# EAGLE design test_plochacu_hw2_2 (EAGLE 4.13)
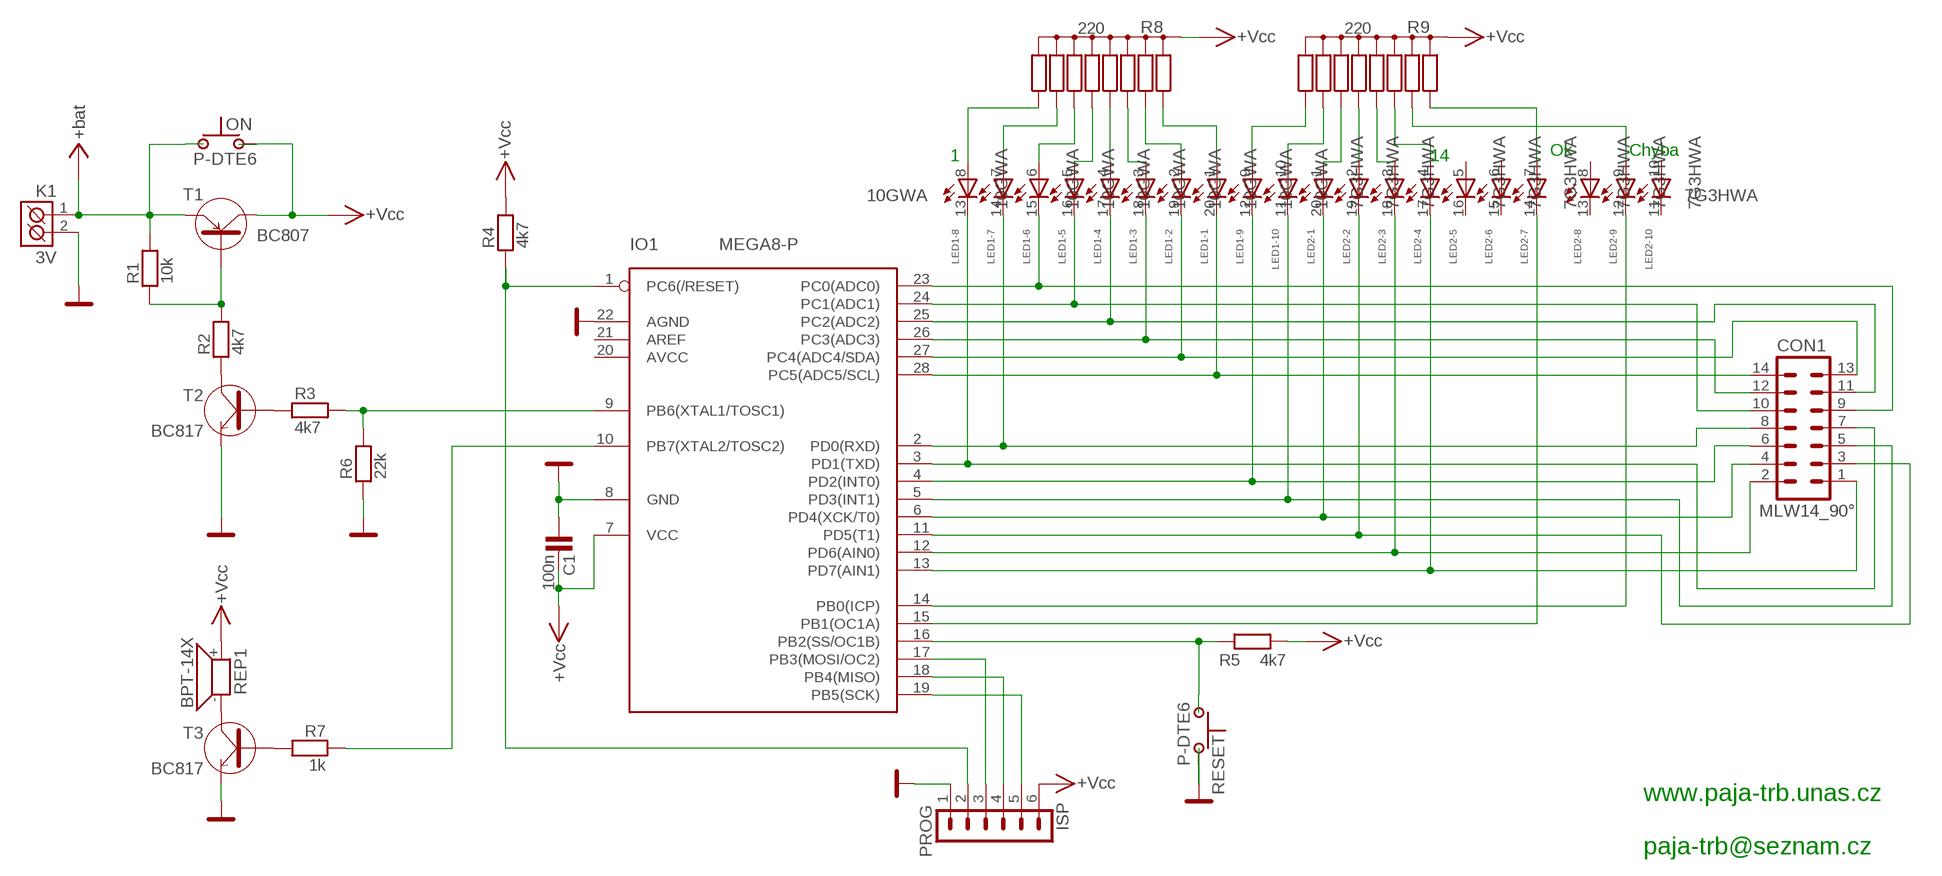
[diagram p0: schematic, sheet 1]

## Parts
C1  100n  C-KERAMIK_SMD_1206  [1206]
CON1  MLW14_90°  [MLW14A]
IO1  MEGA8-P  [DIL28-3]
K1  3V  ARK500/2  [ARK500/2]
LED1  10GWA  LB10  [LB10]
LED2  7G3HWA  LB10  [LB10]
ON  P-DTE6  P-DT6_HRANATY_HRANATY  [P-DTE6]
PROG  ISP  S1G6_JUMP  [S1G6_JUM]
R1  10k  R_SMD_1206  [1206]
R2  4k7  R_SMD_1206  [1206]
R3  4k7  R_SMD_1206  [1206]
R4  4k7  R_SMD_1206  [1206]
R5  4k7  R_SMD_1206  [1206]
R6  22k  R_SMD_1206  [1206]
R7  1k  R_SMD_1206  [1206]
R8  220  RR_8X_A  [RR_8X_A]
R9  220  RR_8X_A  [RR_8X_A]
REP1  BPT-14X  KPE242  [KPE242]
RESET  P-DTE6  P-DT6_HRANATY_HRANATY  [P-DTE6]
T1  BC807  [SOT-23]
T2  BC817  [SOT-23]
T3  BC817  [SOT-23]

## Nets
+BAT: K1.1(K1) ON.1 ON.1A R1.2 T1.2(E) ; supply symbol labelled +bat
+VCC: C1.2 IO1.7(VCC) ON.2 ON.2A PROG.6 R4.2 R5.2 R8.1(R) R9.1(R) REP1.+ T1.3(C) ; supply symbol labelled +Vcc
GND: C1.1 IO1.8(GND) IO1.22(AGND) K1.2(K2) PROG.1 R6.1 RESET.2 RESET.2A T2.2(E) T3.2(E)
N$7: R2.1 T2.3(C)
N$22: LED1.1(-1:A) R8.2(R1)
N$23: LED2.9(-9:A) R9.3(R2)
N$25: LED1.2(-2:A) R8.3(R2)
N$26: CON1.14 IO1.28(PC5(ADC5/SCL)) LED1.20(-1:C)
N$27: CON1.9 IO1.23(PC0(ADC0)) LED1.15(-6:C)
N$28: LED1.3(-3:A) R8.4(R3)
N$29: LED1.4(-4:A) R8.5(R4)
N$42: LED1.5(-5:A) R8.6(R5)
N$43: LED1.6(-6:A) R8.7(R6)
N$44: LED1.7(-7:A) R8.8(R7)
N$45: LED1.8(-8:A) R8.9(R8)
N$46: LED1.9(-9:A) R9.9(R8)
N$47: LED1.10(-10:A) R9.8(R7)
N$48: LED2.1(-1:A) R9.7(R6)
N$49: CON1.10 IO1.24(PC1(ADC1)) LED1.16(-5:C)
N$50: CON1.11 IO1.25(PC2(ADC2)) LED1.17(-4:C)
N$51: CON1.12 IO1.26(PC3(ADC3)) LED1.18(-3:C)
N$52: CON1.13 IO1.27(PC4(ADC4/SDA)) LED1.19(-2:C)
N$53: LED2.2(-2:A) R9.6(R5)
N$54: LED2.3(-3:A) R9.5(R4)
N$55: LED2.4(-4:A) R9.4(R3)
N$56: LED2.7(-7:A) R9.2(R1)
N$57: CON1.8 IO1.2(PD0(RXD)) LED1.14(-7:C)
N$58: CON1.7 IO1.3(PD1(TXD)) LED1.13(-8:C)
N$59: CON1.6 IO1.4(PD2(INT0)) LED1.12(-9:C)
N$60: CON1.5 IO1.5(PD3(INT1)) LED1.11(-10:C)
N$61: CON1.4 IO1.6(PD4(XCK/T0)) LED2.20(-1:C)
N$62: CON1.3 IO1.11(PD5(T1)) LED2.19(-2:C)
N$63: CON1.2 IO1.12(PD6(AIN0)) LED2.18(-3:C)
N$64: CON1.1 IO1.13(PD7(AIN1)) LED2.17(-4:C)
N$65: IO1.19(PB5(SCK)) PROG.5
N$66: IO1.1(PC6(/RESET)) PROG.2 R4.1
N$67: IO1.17(PB3(MOSI/OC2)) PROG.3
N$68: IO1.18(PB4(MISO)) PROG.4
N$69: IO1.10(PB7(XTAL2/TOSC2)) R7.1
N$70: IO1.14(PB0(ICP)) LED2.12(-9:C)
N$71: REP1.- T3.3(C)
N$72: IO1.15(PB1(OC1A)) LED2.14(-7:C)
N$74: R7.2 T3.1(B)
N$75: R3.1 T2.1(B)
N$76: IO1.9(PB6(XTAL1/TOSC1)) R3.2 R6.2
N$77: R1.1 R2.2 T1.1(B)
TLAC: IO1.16(PB2(SS/OC1B)) R5.1 RESET.1 RESET.1A
Unconnected: IO1.20(AVCC) IO1.21(AREF) LED2.5(-5:A) LED2.6(-6:A) LED2.8(-8:A) LED2.10(-10:A) LED2.11(-10:C) LED2.13(-8:C) LED2.15(-6:C) LED2.16(-5:C)

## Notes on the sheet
- Ok | Chyba
- 1 | 14
- www.paja-trb.unas.cz
- paja-trb@seznam.cz

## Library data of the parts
C1 = #PaJa_20:C-KERAMIK: Kondenzator - keramicky
CON1 = #PaJa_20:MLW14: Konektory MLW - vidlice - 14x
IO1 = atmel-1:MEGA8-P: MICROCONTROLLER 8 Kbytes FLASH 1 kbytes SRAM 512 bytes EEPROM USART 4-channel 10 bit ADC 2-channel 8 bit ADC
K1 = #PaJa_20:ARK500/2: Svorkovnice - roztec 5mm - dvojita
LED1 LED2 = led:LB10: LED BLOCK 10-LED bar graph, DIL, Siemens
ON RESET = #PaJa_22:P-DT6??: Tlacitkovy spinac
PROG = #PaJa_20:S1G6_JUMP: Radove konektory - koliky - 6x
R1-R7 = #PaJa_20:R: Rezistor
R8 R9 = #PaJa_20:RR_8X_A: Odporova sit - 8x - spol. vyvod
REP1 = #PaJa_22:KPE242: Piezo-sirenka - 70dB - 3V az 16V
T1 = #PaJa_22:BC807: SMD tranzistor - PNP - ekv. BC327
T2 T3 = #PaJa_22:BC817: SMD tranzistor - NPN - ekv. BC337

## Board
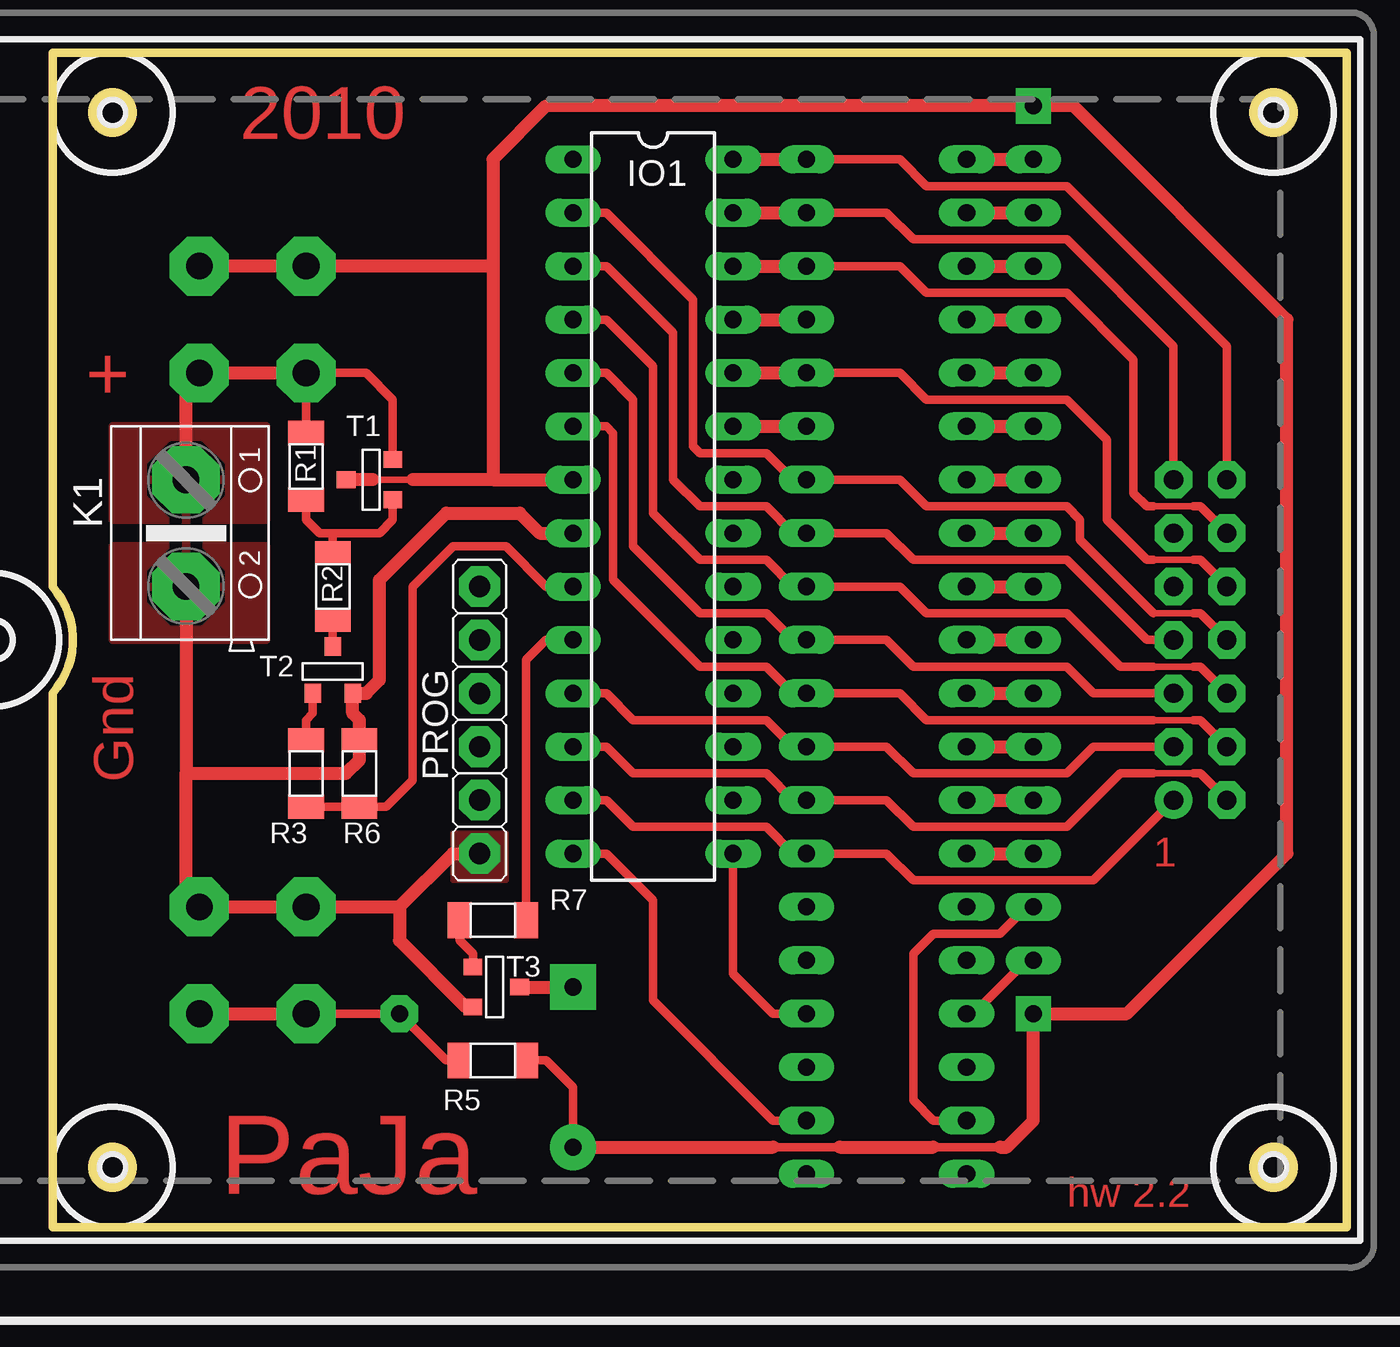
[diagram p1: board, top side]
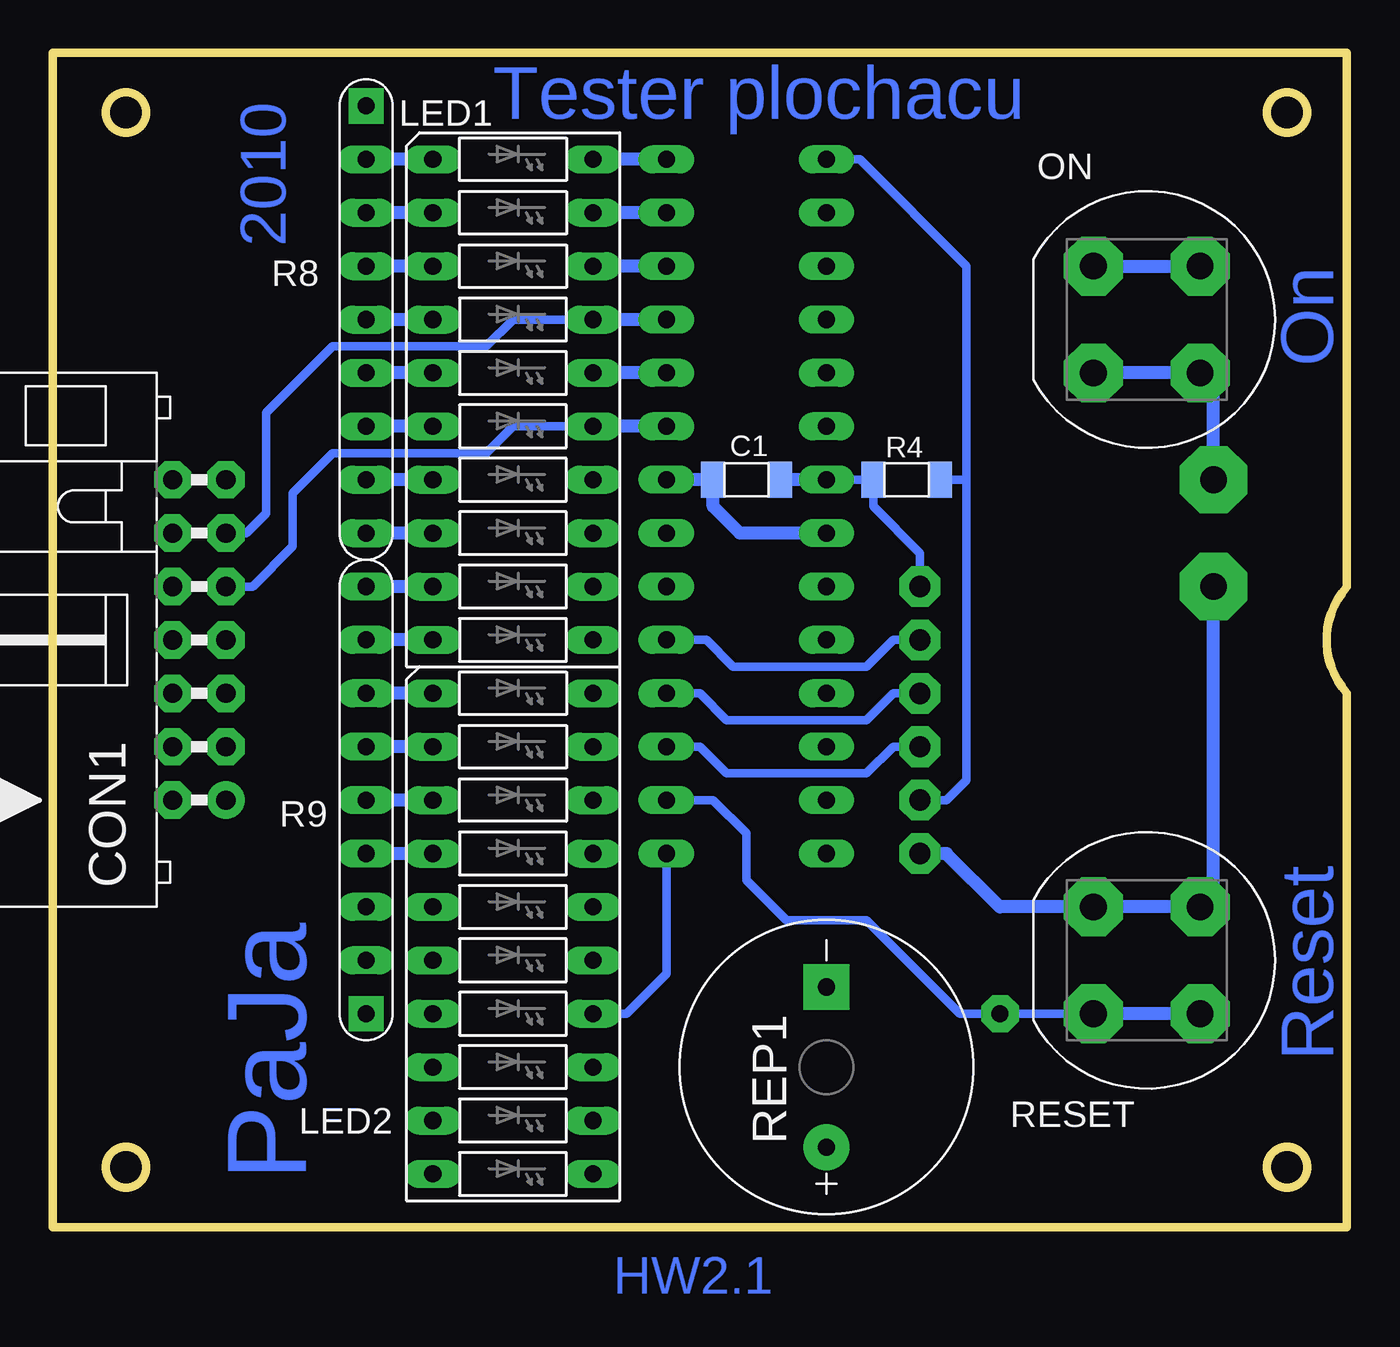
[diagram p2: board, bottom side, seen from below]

Size 61.59 x 55.88 mm. Coordinates in mm from the lower left corner, seen from the top.
Outline: 61.59,55.88 0,55.88 0,30.48 arc-83 0,25.4 0,0 61.59,0 61.59,55.88
Outline: circle at 58.1,2.86 radius 0.95
Outline: circle at 2.86,53.02 radius 0.95
Outline: circle at 2.86,2.86 radius 0.95
Outline: circle at 58.1,53.02 radius 0.95
Copper layers (1*16): Top 0.035mm / dielectric 1.5mm / Bottom 0.035mm
Design rules "default": minimum track width 10mil, minimum drill 24mil, track to track 8mil, track to pad 8mil, pad to pad 8mil, via to via 8mil, smd to smd 8mil, copper to edge 40mil, drill to drill 8mil, minimum pad ring 10mil, minimum via ring 8mil, stop-mask expansion 4mil, vias tented up to drill 0mil, thermal gap 10mil

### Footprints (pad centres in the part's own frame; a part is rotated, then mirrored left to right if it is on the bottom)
1206 = smd 1.143 x 1.702: 1 -1.587,0; 2 1.587,0
MLW14A = drill 0.914 pad 1.778 round: 1 -7.62,-1.27 | drill 0.914 pad 1.778 octagon: 2 -7.62,1.27; 3 -5.08,-1.27; 4 -5.08,1.27; 5 -2.54,-1.27; 6 -2.54,1.27; 7 0,-1.27; 8 0,1.27; 9 2.54,-1.27; 10 2.54,1.27; 11 5.08,-1.27; 12 5.08,1.27; 13 7.62,-1.27; 14 7.62,1.27
DIL28-3 = drill 0.813 long: 1 -16.51,-3.81; 2 -13.97,-3.81; 3 -11.43,-3.81; 4 -8.89,-3.81; 5 -6.35,-3.81; 6 -3.81,-3.81; 7 -1.27,-3.81; 8 1.27,-3.81; 9 3.81,-3.81; 10 6.35,-3.81; 11 8.89,-3.81; 12 11.43,-3.81; 13 13.97,-3.81; 14 16.51,-3.81; 15 16.51,3.81; 16 13.97,3.81; 17 11.43,3.81; 18 8.89,3.81; 19 6.35,3.81; 20 3.81,3.81; 21 1.27,3.81; 22 -1.27,3.81; 23 -3.81,3.81; 24 -6.35,3.81; 25 -8.89,3.81; 26 -11.43,3.81; 27 -13.97,3.81; 28 -16.51,3.81
ARK500/2 = drill 1.27 pad 3.2 octagon: 1 -2.54,0; 2 2.54,0
LB10 = drill 0.813 long: 1 -11.43,-3.81; 2 -8.89,-3.81; 3 -6.35,-3.81; 4 -3.81,-3.81; 5 -1.27,-3.81; 6 1.27,-3.81; 7 3.81,-3.81; 8 6.35,-3.81; 9 8.89,-3.81; 10 11.43,-3.81; 11 11.43,3.81; 12 8.89,3.81; 13 6.35,3.81; 14 3.81,3.81; 15 1.27,3.81; 16 -1.27,3.81; 17 -3.81,3.81; 18 -6.35,3.81; 19 -8.89,3.81; 20 -11.43,3.81
P-DTE6 = drill 1.27 pad 2.8 octagon: 1 -2.54,-2.54; 1A -2.54,2.54; 2 2.54,-2.54; 2A 2.54,2.54
S1G6_JUM = drill 1.016 pad 1.778 octagon: 1 -6.35,0; 2 -3.81,0; 3 -1.27,0; 4 1.27,0; 5 3.81,0; 6 6.35,0
RR_8X_A = drill 0.813 pad 1.676 square: 1 -10.16,0 | drill 0.813 pad 1.27 long: 2 -7.62,0; 3 -5.08,0; 4 -2.54,0; 5 0,0; 6 2.54,0; 7 5.08,0; 8 7.62,0; 9 10.16,0
KPE242 = drill 0.813 pad 2.184 round: + -3.81,0 | drill 0.813 pad 2.184 square: - 3.81,0
SOT-23 = smd 0.787 x 0.889: 1 -0.953,-0.953; 2 0.953,-0.953; 3 0,1.27

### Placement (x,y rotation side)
C1  28.57,35.56 0 bottom
CON1  54.61,27.94 90 bottom
IO1  28.57,34.29 270 top
K1  6.35,33.02 270 top
LED1  39.69,39.37 270 bottom
LED2  39.69,13.97 270 bottom
ON  9.53,43.18 90 bottom
PROG  20.32,24.13 90 top
R1  12.06,36.2 90 top
R2  13.34,30.48 90 top
R3  12.06,21.59 270 top
R4  20.95,35.56 180 bottom
R5  20.95,7.94 0 top
R6  14.61,21.59 270 top
R7  20.95,14.61 180 top
R8  46.67,43.18 270 bottom
R9  46.67,20.32 90 bottom
REP1  24.77,7.62 90 bottom
RESET  9.53,12.7 90 bottom
T1  15.24,35.56 90 top
T2  13.34,26.35 0 top
T3  20.95,11.43 270 top
U$1  [KP20A]  not placed on the board

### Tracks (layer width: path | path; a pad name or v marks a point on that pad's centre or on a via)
+BAT
  Top 0.406: R1.2 ON.1A 14.92,40.64 16.19,39.37 T1.2
  Top 0.61: ON.1A ON.1 6.35,40.01 K1.1
  Bottom 0.61: ON.1A ON.1 6.35,40.01 K1.1
  pour Top: 2.86,33.66 10.16,33.66 10.16,38.1 2.86,38.1
+VCC
  Top 0.305: 17.14,35.56 15.24,35.56
  Top 0.406: 34.29,3.81 37.47,3.81 | 41.91,3.81 45.09,3.81 | R5.2 23.5,7.94 24.77,6.67 REP1.+
  Top 0.61: ON.2 ON.2A 20.95,45.72 | 20.95,45.72 20.95,35.56 | 20.95,35.56 IO1.7 | 20.95,35.56 17.14,35.56 | 15.24,35.56 T1.3 | 20.95,45.72 20.95,50.8 23.5,53.34 R8.1 48.58,53.34 58.74,43.18 58.74,17.78 51.12,10.16 R9.1 46.67,5.08 45.4,3.81 45.09,3.81 | 37.47,3.81 41.91,3.81 | REP1.+ 34.29,3.81
  Bottom 0.406: PROG.6 20.32,32.07 22.54,34.29 R4.2 IO1.7
  Bottom 0.61: IO1.7 C1.2 | ON.2A ON.2
GND  (via drill 0.9 pad 1.93)
  Top 0.406: 19.68,10.48 T3.2
  Top 0.61: IO1.8 23.18,33.02 22.23,33.97 18.73,33.97 15.56,30.8 15.56,26.04 14.92,25.4 T2.2 14.29,24.45 14.61,24.13 R6.1 14.61,22.23 13.97,21.59 6.35,21.59 | 6.35,21.59 6.35,15.88 RESET.2 RESET.2A 16.51,15.24 | PROG.1 | 19.68,10.48 16.51,13.65 16.51,15.24 | 16.51,15.24 19.05,17.78 PROG.1 | K1.2 6.35,21.59
  Bottom 0.61: IO1.22 C1.1 30.16,34.29 28.89,33.02 IO1.8 | PROG.1 | PROG.1 19.05,17.78 16.51,15.24 RESET.2A RESET.2 6.35,15.88 K1.2
  other vias: 20.32,17.78
  pour Top: 2.86,32.38 10.16,32.38 10.16,27.94 2.86,27.94
  pour Top (no thermals, hatched): 19.05,16.51 21.59,16.51 21.59,18.73 19.05,18.73
N$1  (via drill 0.6 pad 0.25)
  other vias: -33.34,69.85
N$2  (via drill 0.9 pad 1.93)
  other vias: 20.32,30.48
N$3  (via drill 0.9 pad 1.93)
  other vias: 20.32,27.94
N$4  (via drill 0.9 pad 1.93)
  other vias: 20.32,25.4
N$5  (via drill 0.9 pad 1.93)
  other vias: 20.32,22.86
N$7
  Top 0.406: T2.3 R2.1
N$22
  Top 0.61: LED1.1 R8.2
  Bottom 0.61: LED1.1 R8.2
N$23
  Top 0.406: R9.3 46.35,15.24 45.09,13.97 41.91,13.97 40.96,13.02 40.96,6.03 41.91,5.08 LED2.9
N$25
  Top 0.61: LED1.2 R8.3
  Bottom 0.61: LED1.2 R8.3
N$26
  Top 0.406: LED1.20 40.32,50.8 41.59,49.53 48.26,49.53 55.88,41.91 CON1.14
  Top 0.61: IO1.28 LED1.20
  Bottom 0.61: IO1.28 LED1.20
N$27
  Top 0.61: IO1.23 LED1.15
  Bottom 0.406: LED1.15 39.69,38.1 40.96,36.83 48.26,36.83 50.16,34.92 50.16,32.38 52.07,30.48 CON1.9
  Bottom 0.61: IO1.23 LED1.15
N$28
  Top 0.61: LED1.3 R8.4
  Bottom 0.61: LED1.3 R8.4
N$29
  Top 0.61: LED1.4 R8.5
  Bottom 0.61: LED1.4 R8.5
N$42
  Top 0.61: LED1.5 R8.6
  Bottom 0.61: LED1.5 R8.6
N$43
  Top 0.61: LED1.6 R8.7
  Bottom 0.61: LED1.6 R8.7
N$44
  Top 0.61: LED1.7 R8.8
  Bottom 0.61: LED1.7 R8.8
N$45
  Top 0.61: LED1.8 R8.9
  Bottom 0.61: LED1.8 R8.9
N$46
  Top 0.61: LED1.9 R9.9
  Bottom 0.61: LED1.9 R9.9
N$47
  Top 0.61: LED1.10 R9.8
  Bottom 0.61: LED1.10 R9.8
N$48
  Top 0.61: LED2.1 R9.7
  Bottom 0.61: LED2.1 R9.7
N$49
  Top 0.305: 52.39,31.75 54.29,31.75
  Top 0.406: LED1.16 40.32,40.64 41.59,39.37 48.26,39.37 50.16,37.47 50.16,34.29 50.16,33.66 52.07,31.75 52.39,31.75 | CON1.10 54.61,31.75 54.29,31.75
  Top 0.61: IO1.24 LED1.16
  Bottom 0.61: IO1.24 LED1.16
N$50
  Top 0.61: IO1.25 LED1.17
  Bottom 0.406: LED1.17 39.69,43.18 40.96,41.91 48.26,41.91 51.44,38.73 51.44,33.97 52.39,33.02 CON1.11
  Bottom 0.61: IO1.25 LED1.17
N$51
  Top 0.305: 52.39,34.29 54.29,34.29
  Top 0.406: LED1.18 40.32,45.72 41.59,44.45 48.26,44.45 51.44,41.27 51.44,35.24 51.44,34.92 52.07,34.29 52.39,34.29 | CON1.12 54.61,34.29 54.29,34.29
  Top 0.61: IO1.26 LED1.18
  Bottom 0.61: IO1.26 LED1.18
N$52
  Top 0.406: LED1.19 39.69,48.26 40.96,46.99 48.26,46.99 53.34,41.91 CON1.13
  Top 0.61: IO1.27 LED1.19
  Bottom 0.61: IO1.27 LED1.19
N$53
  Top 0.61: LED2.2 R9.6
  Bottom 0.61: LED2.2 R9.6
N$54
  Top 0.61: LED2.3 R9.5
  Bottom 0.61: LED2.3 R9.5
N$55
  Top 0.61: LED2.4 R9.4
  Bottom 0.61: LED2.4 R9.4
N$56
  Top 0.406: R9.2 46.35,12.7 43.81,10.16 LED2.7
N$57
  Top 0.305: 52.39,29.21 54.29,29.21
  Top 0.406: IO1.2 26.35,48.26 30.48,44.13 30.48,37.15 30.8,36.83 33.97,36.83 35.24,35.56 LED1.14 40.32,35.56 41.59,34.29 48.26,34.29 48.9,33.66 48.9,32.7 52.39,29.21 | CON1.8 54.61,29.21 54.29,29.21
N$58
  Top 0.406: IO1.3 26.35,45.72 29.53,42.55 29.53,35.56 30.8,34.29 33.97,34.29 35.24,33.02 LED1.13 39.69,33.02 40.96,31.75 48.26,31.75 52.07,27.94 CON1.7
N$59
  Top 0.305: 52.39,26.67 54.29,26.67
  Top 0.406: IO1.4 26.35,43.18 28.57,40.96 28.57,33.97 30.8,31.75 33.97,31.75 35.24,30.48 LED1.12 40.32,30.48 41.59,29.21 48.26,29.21 50.8,26.67 52.39,26.67 | CON1.6 54.61,26.67 54.29,26.67
N$60
  Top 0.406: IO1.5 26.35,40.64 27.62,39.37 27.62,32.38 30.8,29.21 33.97,29.21 35.24,27.94 LED1.11 39.69,27.94 40.96,26.67 48.26,26.67 49.53,25.4 CON1.5
N$61
  Top 0.305: 52.39,24.13 54.29,24.13
  Top 0.406: IO1.6 26.35,38.1 26.67,37.78 26.67,30.8 30.8,26.67 33.97,26.67 35.24,25.4 LED2.20 40.32,25.4 41.59,24.13 48.26,24.13 52.39,24.13 | CON1.4 54.61,24.13 54.29,24.13
N$62
  Top 0.406: IO1.11 26.35,25.4 27.62,24.13 33.97,24.13 35.24,22.86 LED2.19 39.69,22.86 40.96,21.59 48.26,21.59 49.53,22.86 CON1.3
N$63
  Top 0.305: 52.39,21.59 54.29,21.59
  Top 0.406: IO1.12 26.35,22.86 27.62,21.59 33.97,21.59 35.24,20.32 LED2.18 39.69,20.32 40.96,19.05 48.26,19.05 50.8,21.59 52.39,21.59 | CON1.2 54.61,21.59 54.29,21.59
N$64
  Top 0.406: IO1.13 26.35,20.32 27.62,19.05 33.97,19.05 35.24,17.78 LED2.17 39.69,17.78 40.96,16.51 49.53,16.51 CON1.1
N$65
  Bottom 0.406: PROG.5 21.59,27.94 22.86,26.67 29.21,26.67 30.48,27.94 IO1.19
N$66  (via drill 0.9 pad 1.93)
  Bottom 0.406: PROG.2 | 18.1,35.56 18.1,45.72 23.18,50.8 IO1.1 | 18.1,35.56 R4.1 | 18.1,35.56 18.1,21.27 19.05,20.32 PROG.2
  other vias: 20.32,20.32
N$67
  Bottom 0.406: PROG.3 21.59,22.86 22.86,21.59 29.53,21.59 30.8,22.86 IO1.17
N$68
  Bottom 0.406: PROG.4 21.59,25.4 22.86,24.13 29.53,24.13 30.8,25.4 IO1.18
N$69
  Top 0.406: IO1.10 23.5,27.94 22.54,26.99 R7.1
N$70
  Top 0.406: IO1.14 26.35,17.78 28.57,15.56 28.57,10.79 34.29,5.08 LED2.12
N$71
  Top 0.61: T3.3 REP1.-
N$72
  Top 0.406: IO1.15 32.38,12.06 34.29,10.16 LED2.14
  Bottom 0.406: IO1.15 32.38,12.06 34.29,10.16 LED2.14
N$74
  Top 0.406: T3.1 20,13.02 19.37,13.65 R7.2
N$75
  Top 0.406: T2.1 12.38,24.45 12.06,24.13 R3.1
N$76
  Top 0.406: IO1.9 23.5,30.48 21.59,32.38 19.05,32.38 17.14,30.48 17.14,21.27 15.88,20 R6.2 R3.2
N$77
  Top 0.406: R1.1 12.06,33.66 12.7,33.02 13.34,33.02 | 13.34,33.02 15.56,33.02 16.19,33.66 T1.1 | R2.2 13.34,33.02
TLAC  (via drill 0.81 pad 1.78)
  Top 0.406: RESET.1A v16.51,10.16 18.73,7.94 R5.1
  Top 0.61: RESET.1 RESET.1A
  Bottom 0.406: RESET.1A v16.51,10.16 18.41,10.16 22.86,14.61 26.67,14.61 28.57,16.51 28.57,18.73 30.16,20.32 IO1.16
  Bottom 0.61: RESET.1 RESET.1A

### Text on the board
Top: 2010 | + | Gnd | 1 | PaJa | hw 2.2
Bottom: Tester plochacu | 2010 | On | Reset | PaJa | HW2.1
Popisy: Tester plochých kabelu | Chyba | 14 | 1 | PaJa | 1 | 1 | 14 | 1 | Zapni | Tester plochých kabelu | Reset | Zapni | 14 | 14 | Reset | 2010 | Chyba | PaJa | 2010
